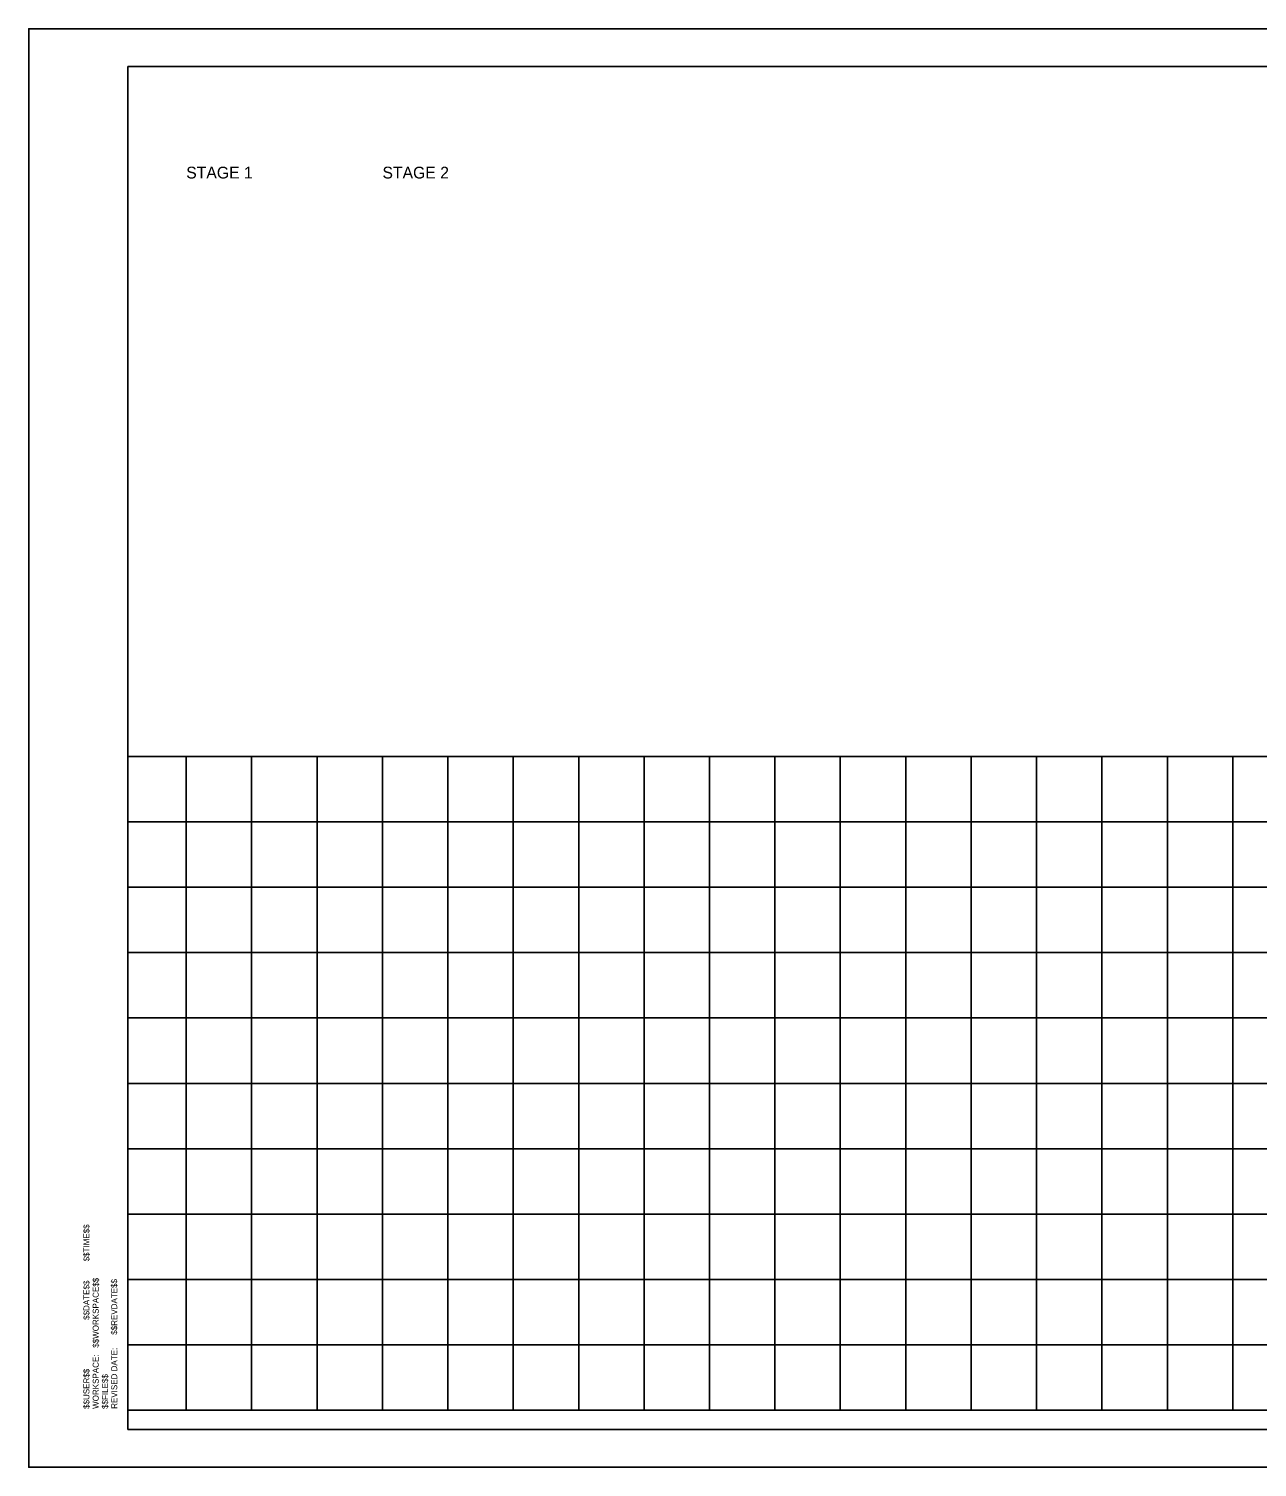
# Model space of a CAD drawing. Extents: x 0 to 1228740, y 0 to 152440.
# Drawn here: x 0 to 18.78, y 0 to 22 of the extents above; entities that cross this region are included whole.
import ezdxf

# ---------------------------------------------------------------- set-up
doc = ezdxf.new("R2010")
doc.units = 0
for name, color, linetype in [('G-TBLK', 7, 'Continuous'), ('R_Border', 7, 'Continuous'), ('R_Grid', 7, 'Continuous'), ('R_XS_EARTHWORK_STAGE1', 7, 'Continuous'), ('R_XS_EARTHWORK_STAGE2', 7, 'Continuous')]:
    doc.layers.add(name, color=color, linetype=linetype)

msp = doc.modelspace()

# ---------------------------------------------------------------- linework, layer by layer
at = {"layer": 'R_Border'}
for p, q in [((1.516, 21.423), (33.423, 21.423)), ((1.516, 0.577), (1.516, 21.423)), ((33.423, 0.577), (1.516, 0.577))]:
    msp.add_line(p, q, dxfattribs=at)
msp.add_lwpolyline([(34, 22), (0, 22), (0, 0), (34, 0)], close=True, dxfattribs=at)
at = {"layer": 'R_Grid'}
for p, q in [((33.423, 10.871), (1.516, 10.871)), ((2.407, 0.871), (2.407, 10.871)), ((3.407, 0.871), (3.407, 10.871)), ((4.407, 0.871), (4.407, 10.871)), ((5.407, 0.871), (5.407, 10.871)), ((6.407, 0.871), (6.407, 10.871)), ((7.407, 0.871), (7.407, 10.871)), ((8.407, 0.871), (8.407, 10.871)), ((9.407, 0.871), (9.407, 10.871)), ((10.407, 0.871), (10.407, 10.871)), ((11.407, 0.871), (11.407, 10.871)), ((12.407, 0.871), (12.407, 10.871)), ((13.407, 0.871), (13.407, 10.871)), ((14.407, 0.871), (14.407, 10.871)), ((15.407, 0.871), (15.407, 10.871)), ((16.407, 0.871), (16.407, 10.871)), ((17.407, 0.871), (17.407, 10.871)), ((18.407, 0.871), (18.407, 10.871)), ((33.423, 9.871), (1.516, 9.871)), ((33.423, 8.871), (1.516, 8.871)), ((33.423, 7.871), (1.516, 7.871)), ((33.423, 6.871), (1.516, 6.871)), ((33.423, 5.871), (1.516, 5.871)), ((33.423, 4.871), (1.516, 4.871)), ((33.423, 3.871), (1.516, 3.871)), ((33.423, 2.871), (1.516, 2.871)), ((33.423, 1.871), (1.516, 1.871)), ((33.423, 0.871), (1.516, 0.871))]:
    msp.add_line(p, q, dxfattribs=at)

# ---------------------------------------------------------------- texts
at = {"layer": 'G-TBLK'}
for s, p in [('$$TIME$$', (0.927, 3.148)), ('$$WORKSPACE$$', (1.069, 1.827)), ('$$REVDATE$$', (1.352, 2.026)), ('$$DATE$$', (0.927, 2.254)), ('REVISED DATE:', (1.352, 0.893)), ('WORKSPACE:', (1.069, 0.892)), ('$$USER$$', (0.927, 0.892)), ('$$FILE$$', (1.211, 0.892))]:
    msp.add_text(s, height=0.0918, rotation=90, dxfattribs=at).set_placement(p)
at = {"layer": 'R_XS_EARTHWORK_STAGE1'}
msp.add_text('STAGE 1', height=0.18, dxfattribs=at).set_placement((2.407, 19.71))
at = {"layer": 'R_XS_EARTHWORK_STAGE2'}
msp.add_text('STAGE 2', height=0.18, dxfattribs=at).set_placement((5.407, 19.71))

doc.saveas('drawing.dxf')
